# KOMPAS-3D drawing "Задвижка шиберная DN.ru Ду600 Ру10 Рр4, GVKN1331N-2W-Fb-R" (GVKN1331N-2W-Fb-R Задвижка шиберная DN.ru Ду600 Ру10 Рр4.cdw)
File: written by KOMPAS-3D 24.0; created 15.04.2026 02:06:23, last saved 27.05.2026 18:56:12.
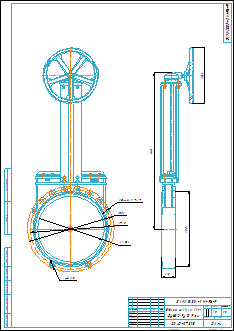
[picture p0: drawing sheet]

Document properties: Автор: DN.ru; Форматы листов документа: A2; Полное имя файла: GVKN1331N-2W-Fb-R Задвижка шиберная DN.ru Ду600 Ру10 Рр4.m3d; Масса: 252; Наименование: Задвижка шиберная DN.ru Ду600 Ру10 Рр4; Количество листов документа: 1; Примечание: D040-07325

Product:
- Part/product: Задвижка шиберная DN.ru Ду600 Ру10 Рр4  | designation GVKN1331N-2W-Fb-R
    Масса: 252
    Раздел спецификации: Прочие изделия
    Примечание: D040-07325

Views: Вид 1, Вид:1, Проекционный вид 2
Referenced files in C:\Работа\GVKN1331N-2W-Fb-R Задвижка шиберная DN.ru Ду400-600 Ру10\DN400\: GVKN1331N-2W-Fb-R Задвижка шиберная DN.ru Ду400 Ру10.m3d
Referenced files in E:\Работа\Зайцев\АУТСОРС\Даня\GVKN1331N-2W-Fb-R Задвижка шиберная DN.ru Ду400-600 Ру4-6\исходные материалы\DN600\DN600\: GVKN1331N-2W-Fb-R Задвижка шиберная DN.ru Ду600 Ру10 Рр4.m3d
Referenced files in C:\Program Files\ASCON\KOMPAS-3D v24\Templates\: Чертеж_DN.ru.cdt
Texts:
  GVKN1331N-2W-Fb-R
  Чертеж_DN.ru.cdt
  Задвижка шиберная DN.ru
  Ду600 Ру10 Рр4
  Задвижка шиберная DN.ru Ду600 Ру10 Рр4
  GVKN1331N-2W-Fb-R Задвижка шиберная DN.ru Ду600 Ру10 Рр4
Dimensions and other numbers on the sheet: 0; 3; 2; 4; 600; 780; 725; 16 отв.; 27; 2 отв.; 30; 1; 1410; 682; 125; 500; 1:5; 252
